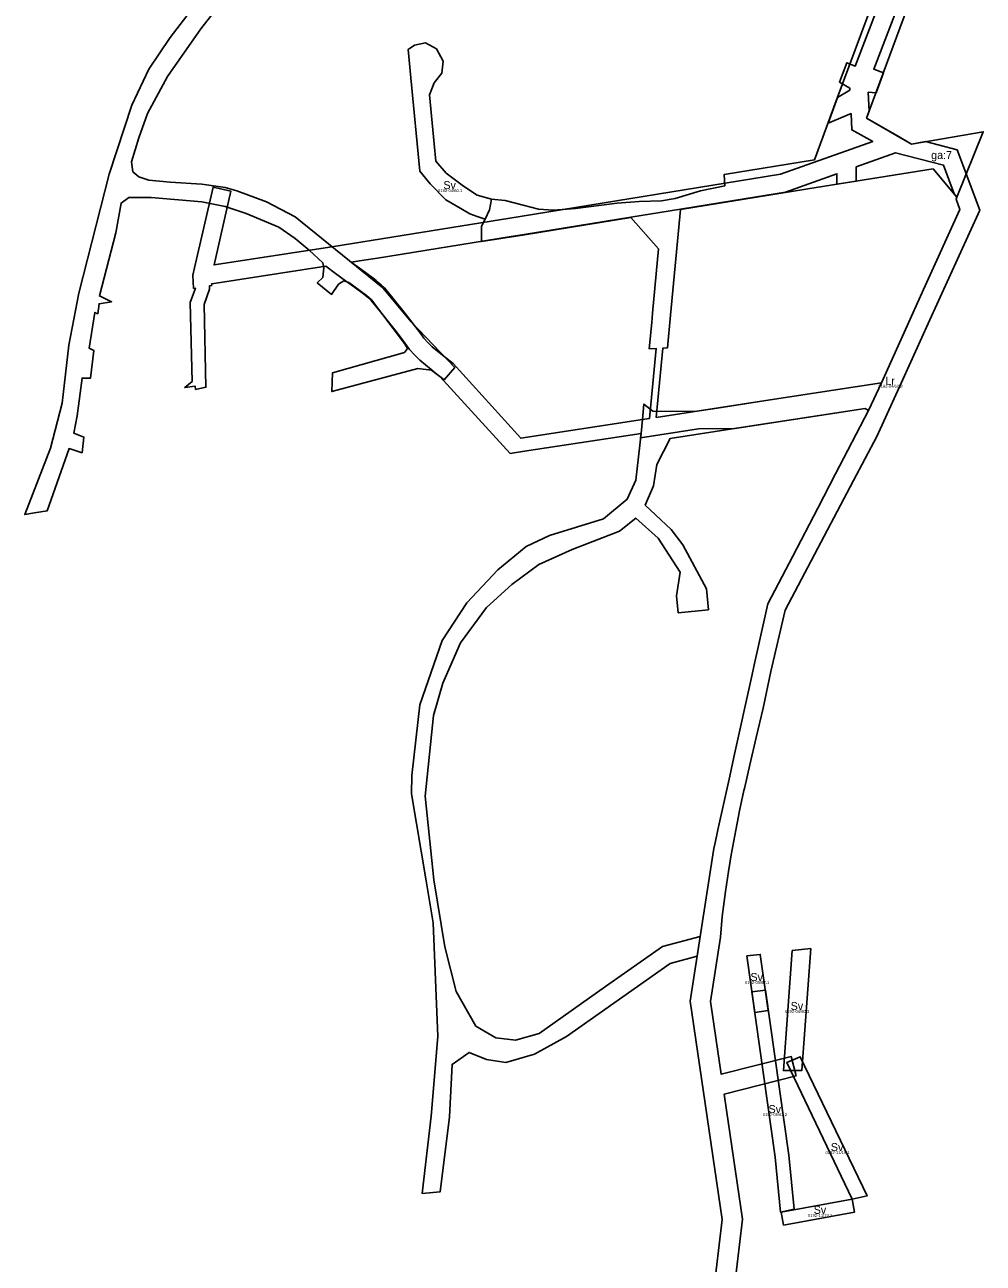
# Model space of a CAD drawing. Extents: x 140791 to 143631, y 6542790 to 6549933.
# Drawn here: x 142278 to 142697, y 6548988 to 6549529 of the extents above; entities that cross this region are included whole.
import ezdxf

# ---------------------------------------------------------------- set-up
doc = ezdxf.new("R2010")
doc.units = 0
for name, color, linetype in [('RATT Aktbeteckning för ledningsrätt', 7, 'Continuous'), ('RATT Aktbeteckning för servitut', 7, 'Continuous'), ('RATT Beteckning för gemensammhetsanläggning', 7, 'Continuous'), ('RATT Beteckning för ledningsrätt', 7, 'Continuous'), ('RATT Beteckning för servitut', 7, 'Continuous'), ('RATT Gemensamhetsanläggningsgräns', 7, 'Continuous'), ('RATT Ledningsrättsgräns', 7, 'Continuous'), ('RATT Servitutsgräns', 7, 'Continuous')]:
    doc.layers.add(name, color=color, linetype=linetype)

msp = doc.modelspace()

# ---------------------------------------------------------------- linework, layer by layer
at = {"layer": 'RATT Gemensamhetsanläggningsgräns'}
for points in [[(142672.7, 6549560.85), (142660.55, 6549527.94), (142645.98, 6549488.53), (142665.56, 6549477.24), (142697, 6549482.58), (142685.47, 6549453.99), (142675.03, 6549466.45), (142620.32, 6549457.6), (142564.58, 6549448.57), (142560.21, 6549402.42), (142558.86, 6549388.11), (142556.77, 6549387.97), (142553.94, 6549357.7), (142570.83, 6549360.29), (142601.88, 6549365.05), (142652.51, 6549372.82), (142646.84, 6549360.76), (142645.32, 6549361.6), (142592.87, 6549353.55), (142560.08, 6549348.53), (142554.13, 6549337.13), (142552.68, 6549327.84), (142549.16, 6549319.33), (142560.47, 6549308.72), (142565.55, 6549301.97), (142575.89, 6549282.72), (142576.75, 6549273.6), (142563.53, 6549272.28), (142562.82, 6549279.73), (142564.38, 6549290.1), (142554.8, 6549304.98), (142544.96, 6549313.72), (142537.9, 6549308.03), (142517.16, 6549299.97), (142502.52, 6549293.38), (142490.75, 6549284.65), (142479.65, 6549274.56), (142468.34, 6549259.15), (142460.59, 6549241.58), (142456.45, 6549227.35), (142452.85, 6549192.17), (142456.58, 6549155.55), (142461.42, 6549126.31), (142466.41, 6549106.65), (142474.97, 6549091.58), (142483.71, 6549086.48), (142492.44, 6549085.39), (142502.68, 6549088.36), (142531.78, 6549108.86), (142556.61, 6549126.35), (142573.13, 6549130.72), (142571.8, 6549122.1), (142560.05, 6549118.98), (142514.61, 6549086.98), (142500.67, 6549079.26), (142488.21, 6549075.6), (142479.63, 6549077.02), (142472.07, 6549080.11), (142464.61, 6549074.82), (142463.51, 6549051.87), (142459.43, 6549019.13), (142451.57, 6549018.35), (142455.47, 6549052.13), (142458.44, 6549087), (142456.32, 6549136.76), (142453.34, 6549155.04), (142446.88, 6549193.09), (142446.95, 6549201.22), (142450.51, 6549232.09), (142460.25, 6549260.11), (142471.01, 6549276.69), (142484.67, 6549291.08), (142497.07, 6549301.23), (142507.25, 6549306.05), (142530.87, 6549313.41), (142541.28, 6549321.91), (142545.01, 6549330.21), (142547.29, 6549350.61), (142547.92, 6549356.78), (142551.05, 6549357.26), (142553.92, 6549387.81), (142550.85, 6549387.63), (142551.95, 6549399.26), (142552.33, 6549403.25), (142555, 6549431.39), (142542.85, 6549445.06), (142496.26, 6549437.52), (142477.43, 6549434.56), (142477.43, 6549441.35), (142479.11, 6549444.39), (142481.01, 6549448.51), (142481.89, 6549453.14), (142487.92, 6549452.57), (142495.65, 6549450.58), (142502.37, 6549448.77), (142509.02, 6549448.27), (142518.57, 6549449.07), (142536.84, 6549451.36), (142546.5, 6549452.08), (142556.28, 6549452.44), (142562.23, 6549453.47), (142573.33, 6549456.79), (142583.89, 6549458.96), (142583.6, 6549463.88), (142623.15, 6549470.33), (142632.71, 6549496.13), (142646.45, 6549533.24)], [(142374.25, 6549552.66), (142354.65, 6549527.67), (142340.09, 6549506.79), (142331.31, 6549490.58), (142327.57, 6549479.95), (142324.31, 6549469.45), (142324.99, 6549465.12), (142327.57, 6549462.85), (142331.99, 6549461.39), (142341.26, 6549460.56), (142355.2, 6549459.72), (142365.29, 6549458.28), (142370.52, 6549456.78), (142383.44, 6549451.96), (142396.04, 6549445.37), (142434.31, 6549414.44), (142446.78, 6549399.45), (142465.82, 6549379.57), (142461.1, 6549374.2), (142455.66, 6549378.34), (142449.6, 6549379.15), (142411.97, 6549368.98), (142412.31, 6549377.17), (142443.75, 6549386.11), (142445.15, 6549387.86), (142443.75, 6549390.01), (142429.34, 6549409.1), (142427.21, 6549411.08), (142419.47, 6549416.65), (142417.21, 6549417.43), (142414.94, 6549415.94), (142411.9, 6549411.52), (142405.64, 6549416.6), (142408.01, 6549418.92), (142408.53, 6549423.1), (142408.01, 6549425.32), (142402.05, 6549430.86), (142396.04, 6549435.92), (142388.82, 6549440.84), (142374.48, 6549446.87), (142365.29, 6549449.94), (142355.2, 6549451.92), (142332.93, 6549453.86), (142323.25, 6549453.92), (142319.85, 6549451.4), (142317.51, 6549438.42), (142310.32, 6549410.83), (142315.67, 6549408.31), (142310.22, 6549407.43), (142309.72, 6549403.05), (142308.36, 6549403.59), (142305.89, 6549387.94), (142307.89, 6549386.99), (142306.51, 6549374.88), (142302.78, 6549374.93), (142300.67, 6549358.45), (142299.21, 6549350.79), (142303.56, 6549349.12), (142302.78, 6549342.28), (142297.04, 6549344.1), (142287.44, 6549316.83), (142281.87, 6549315.97), (142277.68, 6549315.24), (142288.92, 6549344.28), (142293.98, 6549363.95), (142297.01, 6549389.25), (142301.33, 6549412.06), (142314.59, 6549464.14), (142324.47, 6549494.18), (142332, 6549509.97), (142341.26, 6549523.89), (142354.87, 6549541.62)]]:
    msp.add_lwpolyline(points, dxfattribs=at)
at = {"layer": 'RATT Ledningsrättsgräns'}
for points in [[(142662.34, 6549544.7), (142649.08, 6549510.05), (142653.33, 6549508.42), (142650.1, 6549499.67), (142646.72, 6549499.85), (142647.11, 6549491.58), (142645.98, 6549488.53), (142659.43, 6549480.77), (142665.56, 6549477.24), (142671.71, 6549478.29), (142685.62, 6549474.74), (142695.46, 6549448.26), (142672.96, 6549398.82), (142661.78, 6549374.24), (142650.46, 6549349.37), (142640.29, 6549330.16), (142610.27, 6549273.45), (142604.14, 6549246.64), (142600.67, 6549230.65), (142597.59, 6549217.79), (142594.83, 6549205.82), (142592.49, 6549195.47), (142592.32, 6549194.61), (142590.42, 6549185.63), (142586.77, 6549166.49), (142585.53, 6549159.13), (142584.18, 6549150.44), (142582.76, 6549139.55), (142582.02, 6549130.43), (142577.7, 6549102.4), (142582.39, 6549070.51), (142613.02, 6549078.23), (142615.15, 6549069.78), (142583.66, 6549061.87), (142584.7, 6549054.77), (142591.71, 6549007.13), (142581.13, 6548918.62)], [(142572.25, 6548918.44), (142582.83, 6549007.01), (142568.8, 6549102.43), (142578.68, 6549166.48), (142579.11, 6549169.25), (142579.65, 6549171.71), (142580.91, 6549177.42), (142586.1, 6549200.84), (142587.94, 6549209.16), (142595.97, 6549245.38), (142596.7, 6549248.78), (142598.88, 6549258.54), (142602.82, 6549276.22), (142613.7, 6549297.11), (142624.6, 6549318.05), (142632.37, 6549333.06), (142646.82, 6549360.71), (142645.32, 6549361.6), (142588.31, 6549352.82), (142572.49, 6549352.65), (142547.08, 6549348.74), (142547.29, 6549350.61), (142496.3, 6549342.96), (142490.09, 6549341.99), (142459.29, 6549375.63), (142457.37, 6549377.12), (142455.45, 6549378.62), (142452.96, 6549380.67), (142450.47, 6549382.73), (142448.24, 6549385.03), (142446, 6549387.34), (142444.17, 6549390), (142440.7, 6549394.48), (142437.23, 6549398.96), (142433.24, 6549403.89), (142429.25, 6549408.82), (142428.14, 6549409.81), (142425.81, 6549411.77), (142421.9, 6549414.6), (142417.99, 6549417.42), (142413.68, 6549420.61), (142409.38, 6549423.8), (142359.45, 6549416.16), (142359.44, 6549415.39), (142358.48, 6549415.24), (142358.54, 6549413.84), (142356.12, 6549407.05), (142356.96, 6549370.87), (142352.44, 6549369.94), (142352.22, 6549371.39), (142347.67, 6549370.79), (142350.9, 6549373.35), (142350.09, 6549408.02), (142352.31, 6549414.24), (142351.52, 6549414.15), (142351.28, 6549419.95), (142352.01, 6549423.12), (142360.09, 6549458.41), (142367.89, 6549456.63), (142360.51, 6549424.42), (142412.07, 6549432.3), (142442.78, 6549437.24), (142494.47, 6549445.55), (142608.34, 6549464.01), (142648.67, 6549478.33), (142639.48, 6549483.38), (142639.15, 6549490.53), (142629.12, 6549486.39), (142633.26, 6549497.56), (142638.67, 6549500.8), (142638.63, 6549501.72), (142634.1, 6549504.31), (142637.33, 6549512.77), (142641.02, 6549511.36), (142651.3, 6549538.25)], [(142641.33, 6549467.24), (142641.37, 6549461.01), (142632.97, 6549459.65), (142632.97, 6549464.27), (142610.43, 6549456.26), (142592.39, 6549453.31), (142564.53, 6549448.78), (142542.8, 6549445.25), (142496.22, 6549437.68), (142489.62, 6549436.6), (142432.03, 6549427.41), (142426.06, 6549426.46), (142420.44, 6549425.56), (142426.68, 6549421.01), (142430.65, 6549418.14), (142431.42, 6549417.53), (142432.19, 6549416.92), (142433.63, 6549415.64), (142435.07, 6549414.35), (142439.29, 6549409.14), (142443.51, 6549403.92), (142447.07, 6549399.32), (142450.63, 6549394.72), (142452.21, 6549392.43), (142454.06, 6549390.52), (142455.91, 6549388.61), (142458.18, 6549386.74), (142460.45, 6549384.86), (142465.04, 6549381.29), (142494.7, 6549348.62), (142547.92, 6549356.78), (142548.57, 6549363.56), (142552.41, 6549360.44), (142570.83, 6549360.29), (142580.61, 6549361.79), (142601.88, 6549365.05), (142652.51, 6549372.82), (142671.55, 6549415.24), (142686.81, 6549448.57), (142685.14, 6549453.07), (142685.47, 6549453.99), (142684.24, 6549455.45), (142679.58, 6549468.02), (142658.6, 6549473.37), (142641.33, 6549467.24)]]:
    msp.add_lwpolyline(points, dxfattribs=at)
at = {"layer": 'RATT Servitutsgräns'}
for points in [[(142481.89, 6549453.14), (142481.01, 6549448.51), (142479.11, 6549444.39), (142475.6, 6549445.52), (142472.38, 6549446.75), (142469.16, 6549448.59), (142461.94, 6549452.78), (142455.04, 6549459.87), (142450.56, 6549465.34), (142446.62, 6549506.21), (142445.42, 6549518.63), (142448.12, 6549520.51), (142452.94, 6549521.47), (142457.88, 6549518.86), (142460.79, 6549513.54), (142460.11, 6549508.22), (142456.83, 6549504.05), (142454.7, 6549498.72), (142456.83, 6549477.33), (142457.58, 6549469.72), (142462.08, 6549464.53), (142469.58, 6549458.8), (142475.6, 6549454.87), (142481.89, 6549453.14)], [(142621.54, 6549125.55), (142617.67, 6549072.23), (142609.61, 6549072.12), (142613.42, 6549124.62), (142621.54, 6549125.55)], [(142593.53, 6549122.35), (142599.46, 6549122.91), (142602.96, 6549098.43), (142597.02, 6549097.59), (142593.53, 6549122.35)], [(142595.76, 6549106.5), (142601.7, 6549107.34), (142611.94, 6549035.11), (142614.27, 6549011.54), (142608.27, 6549010.27), (142606, 6549034.26), (142595.76, 6549106.5)], [(142639.6, 6549015.87), (142611.13, 6549075.72), (142616.96, 6549078.19), (142646.15, 6549017.36), (142639.6, 6549015.87)], [(142608.6, 6549010.26), (142609.63, 6549004.56), (142640.63, 6549010.17), (142639.6, 6549015.87), (142608.6, 6549010.26)]]:
    msp.add_lwpolyline(points, dxfattribs=at)

# ---------------------------------------------------------------- texts
at = {"layer": 'RATT Aktbeteckning för ledningsrätt'}
msp.add_text('0192-04/60.8', height=1.3, dxfattribs=at).set_placement((142651.1, 6549370.68))
at = {"layer": 'RATT Aktbeteckning för servitut'}
for s, p in [('0192-04/60.1', (142458.47, 6549456.26)), ('0192-05/62.1', (142592.77, 6549110.01)), ('0192-04/60.3', (142610.26, 6549097.33)), ('0192-05/62.2', (142600.59, 6549052.25)), ('0192-11/19.1', (142627.98, 6549035.63)), ('0192-11/19.2', (142620.35, 6549008.18))]:
    msp.add_text(s, height=1.3, dxfattribs=at).set_placement(p)
at = {"layer": 'RATT Beteckning för gemensammhetsanläggning'}
msp.add_text('ga:7', height=3.5, dxfattribs=at).set_placement((142674.22, 6549470.69))
at = {"layer": 'RATT Beteckning för ledningsrätt'}
msp.add_text('Lr', height=3.5, dxfattribs=at).set_placement((142654.2, 6549371.98))
at = {"layer": 'RATT Beteckning för servitut'}
for p in [(142460.83, 6549457.56), (142595.13, 6549111.31), (142612.75, 6549098.63), (142603.07, 6549053.55), (142630.34, 6549036.93), (142622.82, 6549009.48)]:
    msp.add_text('Sv', height=3.5, dxfattribs=at).set_placement(p)

doc.saveas('drawing.dxf')
